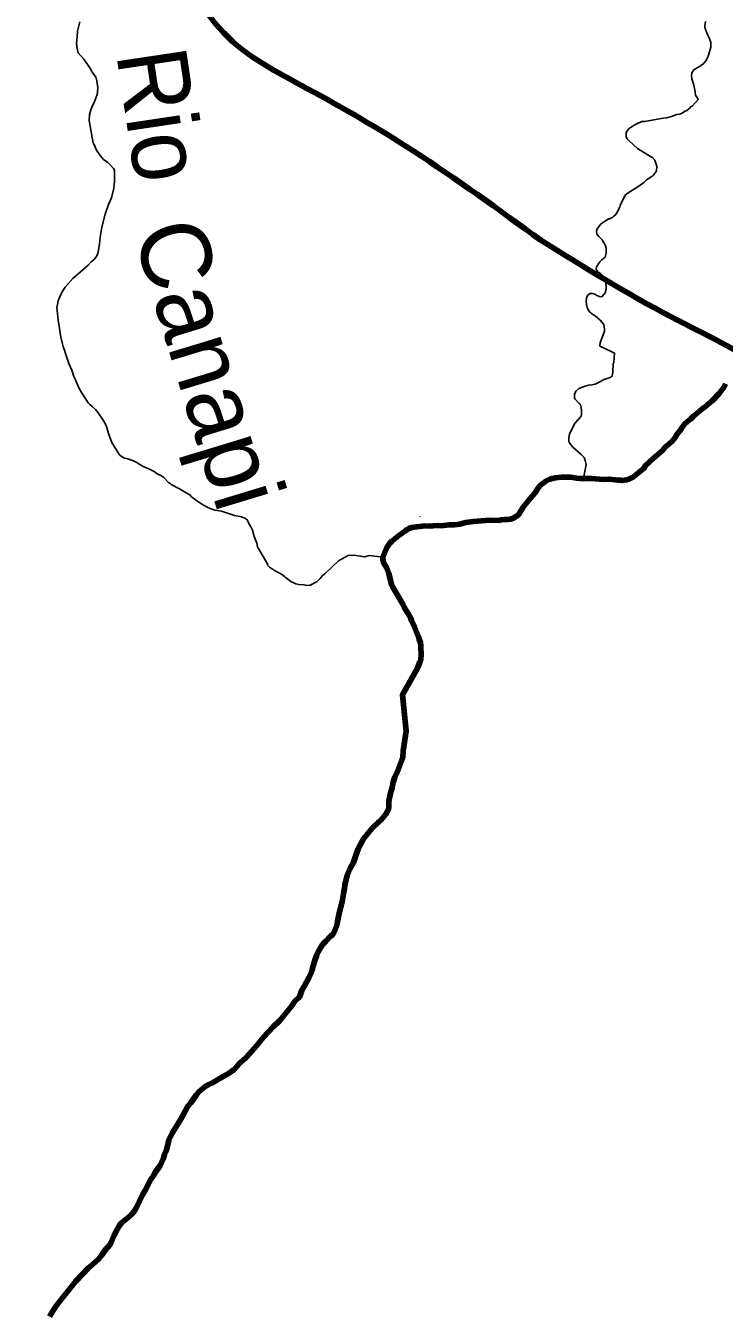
# Model space of a CAD drawing. Extents: x -1643653 to 4543381, y 1624270 to 13878484.
# Drawn here: x 652294 to 657299, y 8967746 to 8976936 of the extents above; entities that cross this region are included whole.
import ezdxf
from ezdxf.enums import TextEntityAlignment as Align

# ---------------------------------------------------------------- set-up
doc = ezdxf.new("R2010")
doc.units = 0
doc.header["$LTSCALE"] = 200
for name, color, linetype, lineweight in [('24', 7, 'Continuous', 25), ('26', 7, 'Continuous', 106), ('28', 7, 'Continuous', 53), ('60', 7, 'Continuous', 13), ('9', 7, 'Continuous', 90)]:
    doc.layers.add(name, color=color, linetype=linetype, lineweight=lineweight)
doc.layers.add('49', color=7, linetype='Continuous')

msp = doc.modelspace()

# ---------------------------------------------------------------- linework, layer by layer
at = {"layer": '24'}
for p, q in [((655116.6, 8973422.7), (655117, 8973424.3)), ((654851.3, 8973132), (654755.7, 8973142.7))]:
    msp.add_line(p, q, dxfattribs=at)
for points in [[(652799.8, 8975280.4), (652809.8, 8975302.2), (652816.1, 8975328.3), (652822.4, 8975374.6), (652826.9, 8975422.5), (652839.8, 8975493.2), (652864.5, 8975587.5), (652888.2, 8975655.6), (652908, 8975704.5), (652925.9, 8975773.4), (652929.4, 8975820.5), (652930.5, 8975902.1), (652923, 8975914.4), (652902.1, 8975937.5), (652881.4, 8975957.1), (652852.2, 8975978.9), (652827.9, 8976005.5), (652801.9, 8976045.7), (652783.3, 8976090.1), (652777.5, 8976093.8), (652748.7, 8976257.8), (652752.2, 8976297.8), (652759.6, 8976332.9), (652774.2, 8976369.2), (652784.3, 8976387.2), (652805.5, 8976443.3), (652809.5, 8976460.7), (652811.3, 8976493), (652801.1, 8976555.8), (652798.8, 8976558), (652796.5, 8976566.6), (652771.4, 8976603.6), (652757.2, 8976628.1), (652709.4, 8976696.7), (652669.3, 8976741.1), (652663.9, 8976773), (652657.8, 8976807.6), (652663.9, 8976859.5), (652664.9, 8976895.8), (652682.2, 8976964.3)], [(657164.7, 8976965.5), (657159.4, 8976934.9), (657159.4, 8976922.3), (657172.8, 8976885.3), (657195, 8976838.1), (657200.9, 8976815.4), (657201.5, 8976781.6), (657185.6, 8976725.5), (657177.3, 8976704.9), (657165.5, 8976683.5), (657144.4, 8976659), (657138.5, 8976657.5), (657133.7, 8976651.6)], [(657133.7, 8976651.6), (657080.2, 8976620), (657066.2, 8976597.4), (657063.1, 8976576.8), (657066.3, 8976556.2), (657072.5, 8976533.5), (657080.9, 8976509.9), (657090.5, 8976462.8), (657091, 8976439.3), (657110, 8976410.1), (657110.9, 8976406.4), (657067.4, 8976361), (657056.2, 8976354.8), (657053.5, 8976348.9), (657031.1, 8976329.9), (657013.6, 8976321.3), (656995.6, 8976309.4), (656979.2, 8976303.3), (656959.2, 8976299.6), (656920.6, 8976285.8), (656884.5, 8976276.8), (656845.1, 8976271.2), (656729.4, 8976250.9), (656707.8, 8976249), (656672.3, 8976234.3), (656651.5, 8976222.8), (656618, 8976199.7), (656600.5, 8976181.9), (656595.8, 8976166.3), (656594.8, 8976146.6), (656595.7, 8976138.4), (656602.4, 8976126.5), (656615.7, 8976111), (656677.7, 8976057.2), (656776.5, 8975994.6), (656782.5, 8975993.7), (656799.6, 8975973.9), (656803.7, 8975967.1), (656814.1, 8975929.4), (656813.1, 8975895.9), (656791.5, 8975865.6), (656785.6, 8975862.2), (656783.8, 8975858), (656775.5, 8975856.3), (656772.4, 8975851.8), (656742.2, 8975832.4), (656721.1, 8975813.8), (656679, 8975783.2), (656609.4, 8975739.2), (656588, 8975723), (656553.5, 8975648.5), (656550.6, 8975639.1), (656544.7, 8975630.5), (656542.4, 8975621.5), (656520.2, 8975584), (656507.8, 8975571.5), (656503.7, 8975569.7), (656500.5, 8975566.2), (656496.9, 8975565.1), (656495.3, 8975562.1), (656486.8, 8975559.7), (656479.1, 8975553.8), (656468.9, 8975552.5), (656445.8, 8975536.4), (656445.8, 8975536.4)], [(656445.8, 8975536.4), (656428.1, 8975527.1), (656412.7, 8975513.8), (656400.9, 8975501.1), (656386.7, 8975481.1), (656383.9, 8975464.5), (656385.2, 8975443.3), (656398.8, 8975427.1), (656422.7, 8975403.9), (656434, 8975387.3), (656444.5, 8975366.6), (656451.2, 8975343.8), (656452.2, 8975307.7), (656444.4, 8975279.3), (656420.2, 8975258.8), (656406.9, 8975244.3), (656382, 8975208.4), (656379.8, 8975191.2), (656391.2, 8975173.8), (656397, 8975172), (656400.5, 8975168.9), (656408.8, 8975165.1), (656442.9, 8975127.3), (656450.2, 8975105.1), (656451, 8975049), (656444.2, 8975024.3), (656423.6, 8974996.6), (656411.6, 8974995.5), (656402.2, 8974996.5), (656392.2, 8975002.6), (656384.2, 8975004.6), (656371.7, 8975013.2), (656353.6, 8975017.8), (656334.6, 8975017.5), (656320.6, 8975007.7), (656317.6, 8975003.5), (656311.8, 8974985.1)], [(654755.7, 8973142.7), (654720.6, 8973132.1), (654647.5, 8973144.9), (654604.9, 8973142), (654598.8, 8973140.5), (654534.6, 8973104.9), (654437.3, 8973012.6), (654419.5, 8972998.8), (654403.8, 8972979.2), (654381.6, 8972957.8), (654363, 8972946.1), (654335.2, 8972931.4), (654326.4, 8972929.3), (654308.8, 8972928.4), (654287.9, 8972933.5), (654250.2, 8972934.8), (654229.3, 8972940.7), (654192.4, 8972956.2), (654152.5, 8972986.8), (654147.8, 8972992.5), (654142.1, 8972995.3), (654139, 8973001.3), (654076, 8973035.9), (654041.5, 8973060), (654027.3, 8973074.1), (654028.3, 8973079.5), (653955, 8973206), (653948.8, 8973231.1), (653931.5, 8973279.1), (653918, 8973324.5), (653906.3, 8973348.1), (653892.5, 8973371.7), (653880.9, 8973398.6), (653873.4, 8973402.2), (653869.2, 8973406.6), (653838.8, 8973418.7), (653790.9, 8973428.7), (653697.5, 8973459.4), (653649.6, 8973468.4), (653604, 8973484.9), (653582.4, 8973495.6), (653556.1, 8973510.9), (653509.5, 8973541.4), (653482.9, 8973561.9), (653470.5, 8973577.6), (653442.6, 8973592.3), (653395.4, 8973620.1), (653335.2, 8973650.9), (653328.8, 8973657.6), (653317.1, 8973665.3), (653282.9, 8973700.4), (653261.2, 8973715), (653237, 8973727.3), (653213.3, 8973743.3), (653191.4, 8973755.3), (653143.5, 8973777.1), (653134.4, 8973779.3), (653111.9, 8973795.2), (653085.1, 8973811.8), (653065.5, 8973821.4), (653019.2, 8973837.3), (653002.9, 8973840.6), (652981, 8973851.6), (652965.9, 8973864.6), (652937, 8973909.3), (652911.1, 8973953), (652887.5, 8974017.3), (652874.5, 8974060.1), (652864.8, 8974083.7), (652850.2, 8974112.8), (652813.3, 8974163.9), (652794.5, 8974187.8), (652771, 8974210.2), (652753.5, 8974223.6), (652741.1, 8974236.2), (652681.1, 8974329.2), (652660, 8974375.6), (652651, 8974399.9), (652639.3, 8974423.5), (652623.5, 8974469.8), (652603.2, 8974516.9), (652579.3, 8974588.4), (652572.8, 8974612), (652562.8, 8974637.3), (652546.2, 8974706.2), (652532.2, 8974799.6), (652526.8, 8974824.9), (652519.2, 8974897.6), (652518.3, 8974918.3), (652521.3, 8974941), (652527.4, 8974967.1), (652535.4, 8974989), (652558, 8975036.1), (652577.2, 8975063.9), (652631.7, 8975125.9), (652648.1, 8975141.2), (652704.5, 8975187.2), (652741, 8975221.5), (652762.8, 8975244.2), (652783.3, 8975259.7), (652799.8, 8975280.4)], [(656311.8, 8974985.1), (656309.9, 8974965.4), (656310.9, 8974936.3), (656314.2, 8974931), (656318.5, 8974912), (656333.2, 8974887.1), (656339.6, 8974883.1), (656344.1, 8974878.5), (656345.9, 8974874.7), (656352.9, 8974872.7), (656357, 8974868.2), (656372.6, 8974857.7), (656410.2, 8974827.3), (656435.2, 8974796.3), (656440.2, 8974762.4), (656440.3, 8974749.1), (656410.3, 8974666), (656407.6, 8974643.7), (656410, 8974639.2), (656419.4, 8974636), (656511, 8974591.7), (656507.5, 8974524.4), (656501.5, 8974515), (656499.2, 8974456.9), (656494.7, 8974426.9), (656479.6, 8974416.5), (656466.4, 8974413.5), (656443.7, 8974405.2), (656396.6, 8974380.7), (656373, 8974370.1), (656349.5, 8974365.7), (656325.9, 8974363.3), (656300.7, 8974356.3), (656256.1, 8974338), (656235.1, 8974319.4), (656224.5, 8974294.9), (656226, 8974270.5), (656228.6, 8974263.7), (656258.3, 8974232.1), (656265, 8974227.3), (656269.2, 8974222.2), (656273.4, 8974202.8), (656276.5, 8974180.1), (656276.6, 8974148.4), (656268.5, 8974134.2), (656264, 8974130.4), (656262.3, 8974125), (656257.6, 8974123.2), (656253.4, 8974116.8), (656244.1, 8974109.9), (656235.6, 8974096.1), (656229.8, 8974092), (656209.8, 8974056.4), (656189, 8974012.7), (656183.6, 8973985.6), (656184.6, 8973963), (656186.9, 8973950), (656191.3, 8973947.8), (656199.2, 8973934.2), (656213.7, 8973918.7), (656274.2, 8973865.6), (656294.1, 8973843.5), (656302.2, 8973822.7), (656307.8, 8973793.6), (656289.8, 8973694.9)]]:
    msp.add_lwpolyline(points, dxfattribs=at)
at = {"layer": '24', "lineweight": 53}
for points in [[(657308, 8974372.1), (657297.1, 8974350.1), (657279, 8974323.5), (657261.3, 8974302.8), (657210.5, 8974250), (657181.7, 8974226.4), (657161.9, 8974207.7), (657140, 8974192), (657118.9, 8974173.4), (657078.2, 8974140.8), (657056.3, 8974119.3), (657035, 8974103.2), (657016, 8974086.2), (656999.6, 8974063.5), (656982.9, 8974036.6), (656963.3, 8974017.4), (656946, 8973988.7), (656926.4, 8973964.7), (656902.1, 8973940.5), (656874.4, 8973917.8), (656856.7, 8973895.3), (656791.9, 8973840.8)], [(656791.9, 8973840.8), (656791.8, 8973840.8), (656728.6, 8973781.9), (656729.8, 8973775.9), (656716.7, 8973763.4), (656647.1, 8973704.9), (656615.1, 8973689.9), (656598.4, 8973684.2), (656598.4, 8973684.2), (656567.2, 8973679.3), (656556.3, 8973683.2), (656536.3, 8973682.5), (656475.8, 8973689.6), (656432.2, 8973686.7), (656347.3, 8973694), (656260.8, 8973695.2), (656240.2, 8973697.3)], [(656240.2, 8973697.3), (656197.4, 8973704.6), (656175.9, 8973703.8), (656133.1, 8973704.7), (656090.3, 8973699.3), (656067.2, 8973694.6), (656047.4, 8973688.6), (656026.8, 8973679.3), (655983.7, 8973648.4), (655968.2, 8973630.5), (655940.3, 8973590.2), (655926.4, 8973572.3), (655907.2, 8973551.6), (655857.4, 8973488), (655825.2, 8973435), (655819.5, 8973432.4), (655817.1, 8973428.1), (655813, 8973426.4), (655807.3, 8973421.2), (655797.6, 8973417.6), (655794, 8973413), (655766.8, 8973403.9), (655745.4, 8973399.7), (655722.2, 8973400.4), (655702.5, 8973398.4), (655680.3, 8973394.3), (655616.9, 8973396.2), (655501.2, 8973386.6), (655443.3, 8973378), (655404.8, 8973367.5), (655366.2, 8973362.1), (655326.8, 8973361.9), (655289.1, 8973358.7), (655269, 8973355.7), (655249.7, 8973356.6), (655212, 8973355.5), (655191.9, 8973353.5), (655154.1, 8973354.5), (655137.5, 8973353.6), (655077.8, 8973346), (655060.3, 8973342.2), (655039.3, 8973335.4), (655029.9, 8973329.2), (655023.6, 8973328.5), (655016.9, 8973321.8), (654963.5, 8973284.3), (654916.4, 8973246.2), (654900.8, 8973228.3), (654881.6, 8973201), (654851.3, 8973132), (654852.3, 8973113.8), (654858.7, 8973088.2), (654878.1, 8973056.9), (654895, 8973014.3), (654909.2, 8972953.2), (654915.3, 8972934.7), (654923.6, 8972916.2), (654947.3, 8972875.3), (654982.1, 8972819.3), (654996.2, 8972794.1), (655005.3, 8972774), (655014.6, 8972757.2), (655044.4, 8972710.5), (655053.7, 8972692), (655056.5, 8972676.5), (655080.1, 8972632.6), (655093.2, 8972594.1), (655109.8, 8972556.3), (655111.9, 8972544), (655121.8, 8972516.9), (655124, 8972498.5), (655124.2, 8972478.4), (655127.3, 8972439.8), (655123.7, 8972391.1), (655118.2, 8972380.4), (655102.9, 8972341.9), (654992.2, 8972144.1), (655019.8, 8971884.2), (654998.6, 8971745.3), (654995, 8971695.3), (654989.7, 8971685.4), (654957.7, 8971597.4), (654937.6, 8971556.5), (654925.2, 8971519.5), (654918.6, 8971481), (654907, 8971442.4), (654896.1, 8971382.9), (654895.8, 8971344.4), (654892, 8971324.4), (654883.1, 8971306.7), (654872.7, 8971291.8), (654840.1, 8971251.1), (654818.4, 8971232.1), (654818.4, 8971232.1), (654777.1, 8971189.8), (654713.1, 8971114), (654675.8, 8971041.8), (654665.8, 8971017.4), (654650.1, 8970966.2), (654641.7, 8970946), (654616.5, 8970899.6)], [(654616.5, 8970899.6), (654597.8, 8970850.8), (654585.3, 8970804.5), (654581.2, 8970781.8), (654578.8, 8970758.3), (654572.6, 8970734.7), (654560.7, 8970664), (654554.4, 8970640.4), (654550, 8970616.9), (654542.2, 8970591.6), (654533, 8970547), (654526.8, 8970523.4), (654524.2, 8970501.2), (654508.2, 8970458.4), (654499, 8970437.8), (654493.5, 8970429), (654477.7, 8970417.1), (654443, 8970382.2), (654421.1, 8970358.3), (654389.5, 8970306.2), (654379.5, 8970284), (654365, 8970242.8), (654351.1, 8970197.8), (654345.4, 8970173.5), (654336.8, 8970149.9), (654324.7, 8970123.6), (654288, 8970056.4), (654272.8, 8970031.9), (654254.6, 8969979.6), (654230.2, 8969960.2), (654218.1, 8969945.2), (654200.3, 8969917.9), (654115.1, 8969812.6), (654066, 8969768.5), (653998.5, 8969693.6), (653949.1, 8969634.7), (653875.5, 8969551.6), (653848.1, 8969526.1), (653826.1, 8969509.2), (653807.7, 8969485.9), (653788.8, 8969465.8), (653781.7, 8969461.6), (653774.9, 8969453.3), (653733.8, 8969425.9), (653708.2, 8969413.9), (653656.8, 8969380.9), (653631.1, 8969367), (653605.4, 8969356.1), (653579.7, 8969340.1), (653534.3, 8969303.2), (653514.9, 8969279.7), (653477.3, 8969225.2), (653456.6, 8969199.3), (653405, 8969106.7), (653344.1, 8969008.1), (653319.5, 8968956.7), (653307.6, 8968905.3), (653300.6, 8968881.3), (653288.5, 8968853.8), (653281.5, 8968827.4), (653256.7, 8968776), (653222.5, 8968726.1), (653207.9, 8968699.7), (653188.9, 8968672.3), (653150.5, 8968597.6), (653133.3, 8968569.4), (653084.6, 8968470), (653068.7, 8968444.2), (653061.9, 8968437.6), (653060, 8968431.6), (653055, 8968429.5), (653045.5, 8968418.5), (652999.2, 8968380.5), (652979.1, 8968362.1), (652966, 8968345), (652949.9, 8968318.3), (652925.3, 8968271.2), (652905.8, 8968224.1), (652891.4, 8968201.3), (652870.7, 8968180.1), (652835.3, 8968129.2), (652814.8, 8968105.2), (652767.5, 8968061.3), (652745.1, 8968043.8), (652652.7, 8967947.3), (652575.9, 8967853), (652512.8, 8967770.6), (652464.1, 8967693.3)]]:
    msp.add_lwpolyline(points, dxfattribs=at)
at = {"layer": '26'}
for points in [[(593042.9, 8976356.4), (593459.4, 8976419.7), (594161.8, 8976760.1), (594545.8, 8977114.6), (594814.3, 8977291.5), (596052.8, 8977846), (596780.5, 8978160.9), (597647.4, 8978322.7), (598691.5, 8978280.2), (599825, 8978301), (600207.2, 8978324.8), (600219.9, 8978324.8), (601225.9, 8978295.2), (602040.5, 8978228.3), (602729, 8978352.6), (603275.7, 8978615.7), (603826.1, 8978691.5), (605382.2, 8979104.7), (606925.6, 8979530.7), (607614.7, 8979782.2), (608494.2, 8979905.8), (609628.7, 8980104.6), (610966.5, 8980200.8), (612239.3, 8980081.1), (613131.4, 8980179.2), (614149.6, 8980073.3), (614581.8, 8979931.6), (616361, 8979275.7), (617566.6, 8978533.2), (618237.8, 8977881.9), (618833.2, 8977319.9), (619759.6, 8976743.8), (620623, 8976295.2), (621512.5, 8975960.9), (621945, 8975870.1), (622544.2, 8975982.1), (622735.8, 8976070.3), (623374, 8976322), (623974.5, 8976675.6), (624627.1, 8977219.8), (625050.7, 8977803), (625410.5, 8978361.1), (625972.2, 8978587.6), (626239.9, 8978637.4), (628239.2, 8978616.5), (629272.1, 8978853.8), (630051.8, 8979346.6), (630703.5, 8979738.1), (631164.1, 8980105), (631534.8, 8980357.8), (632185.7, 8980596.8), (632989, 8980758.8), (633690, 8980870.4), (634328.2, 8981109.3), (634980.1, 8981526.3), (636460.7, 8982117.9), (637495.4, 8982660.5), (638159.4, 8982975.7), (638593.8, 8983228.2), (639449.6, 8983669.8), (641371.6, 8983483.9), (642032.9, 8983315.8), (642528.8, 8983186.6), (643277.3, 8982687.6), (644168, 8982544), (644675.9, 8982274.9), (645321.7, 8981636.4), (645853, 8981011.1), (646805.1, 8980473.1), (647606.1, 8980240.8), (648482.7, 8979868.5), (649626.6, 8979469.5), (650871.6, 8978943), (651404, 8978495.7), (652521.8, 8977995.2), (653308.2, 8977445.1), (653712.6, 8976883.9), (654308.9, 8976487.2), (655070.4, 8976039), (655983.7, 8975399.4)], [(655983.7, 8975399.4), (656923, 8974848.7), (657608.5, 8974464.4), (658343, 8973736.5), (658963.6, 8973136.3), (659596.6, 8972485.1), (660330.5, 8971655.5), (660495.7, 8971591.2), (661115.6, 8970863.8), (661404.1, 8970086.9), (661693.8, 8969526.2), (662110.5, 8968901.3), (662312.2, 8968544.4), (662816.6, 8967664.9), (663042.2, 8967040.8), (663203.6, 8966302.6), (663365.3, 8965640.7), (663833.2, 8965053.8), (664099.5, 8964849.2), (664772, 8964426.8), (665496.3, 8964144), (666463.4, 8964000.2), (667623.1, 8964148), (668184.3, 8964285.6), (669317.4, 8964230), (670221.1, 8964150), (671187.7, 8963917.1), (671823.3, 8963711.1), (672497.1, 8963517.5), (673386.9, 8963221.4), (674492.1, 8962733.6), (675125.5, 8962146), (675556, 8961711.9), (676150.3, 8960959.1), (676174.9, 8960921)]]:
    msp.add_spline(points, degree=3, dxfattribs=at)
at = {"layer": '28'}
for points in [[(655983.7, 8975399.4), (655070.4, 8976039), (654308.9, 8976487.2), (653712.6, 8976883.9), (653308.2, 8977445.1), (652521.8, 8977995.2), (651404, 8978495.7), (650871.6, 8978943), (649626.6, 8979469.5), (648482.7, 8979868.5), (647606.1, 8980240.8), (646805.1, 8980473.1), (645853, 8981011.1), (645321.7, 8981636.4), (644675.9, 8982274.9), (644540.6, 8982372.7)], [(676174.9, 8960921), (676150.3, 8960959.1), (675556, 8961711.9), (675125.5, 8962146), (674492.1, 8962733.6), (673386.9, 8963221.4), (672497.1, 8963517.5), (671823.3, 8963711.1), (671187.7, 8963917.1), (670221.1, 8964150), (669317.4, 8964230), (668184.3, 8964285.6), (667623.1, 8964148), (666463.4, 8964000.2), (665496.3, 8964144), (664772, 8964426.8), (664099.5, 8964849.2), (663833.2, 8965053.8), (663365.3, 8965640.7), (663203.6, 8966302.6), (663042.2, 8967040.8), (662816.6, 8967664.9), (662312.2, 8968544.4), (662110.5, 8968901.3), (661693.8, 8969526.2), (661404.1, 8970086.9), (661115.6, 8970863.8), (660495.7, 8971591.2), (660330.5, 8971655.5), (659596.6, 8972485.1), (658963.6, 8973136.3), (658343, 8973736.5), (657608.5, 8974464.4), (656923, 8974848.7), (655983.7, 8975399.4)]]:
    msp.add_spline(points, degree=3, dxfattribs=at)
at = {"layer": '60', "lineweight": 25}
msp.add_spline([(814781, 9009175.5), (814787.2, 9009173.4), (814796.9, 9009173.4), (814799.4, 9009172.4), (814805.1, 9009174.5), (814805.6, 9009176.5), (814811.7, 9009179.5), (814811.7, 9009179.5), (814801.5, 9009181), (814790.7, 9009181.5), (814784.1, 9009183.1), (814777.4, 9009185.1), (814778.4, 9009175.5)], degree=3, dxfattribs=at)
at = {"layer": '9'}
for points in [[(657308, 8974372.1), (657297.1, 8974350.1), (657279, 8974323.5), (657261.3, 8974302.8), (657210.5, 8974250), (657181.7, 8974226.4), (657161.9, 8974207.7), (657140, 8974192), (657118.9, 8974173.4), (657078.2, 8974140.8), (657056.3, 8974119.3), (657035, 8974103.2), (657016, 8974086.2), (656999.6, 8974063.5), (656982.9, 8974036.6), (656963.3, 8974017.4), (656946, 8973988.7), (656926.4, 8973964.7), (656902.1, 8973940.5), (656874.4, 8973917.8), (656856.7, 8973895.3), (656791.9, 8973840.8)], [(656791.9, 8973840.8), (656791.8, 8973840.8), (656728.6, 8973781.9), (656729.8, 8973775.9), (656716.7, 8973763.4), (656647.1, 8973704.9), (656615.1, 8973689.9), (656598.4, 8973684.2), (656598.4, 8973684.2), (656567.2, 8973679.3), (656556.3, 8973683.2), (656536.3, 8973682.5), (656475.8, 8973689.6), (656432.2, 8973686.7), (656347.3, 8973694), (656260.8, 8973695.2), (656240.2, 8973697.3)], [(656240.2, 8973697.3), (656197.4, 8973704.6), (656175.9, 8973703.8), (656133.1, 8973704.7), (656090.3, 8973699.3), (656067.2, 8973694.6), (656047.4, 8973688.6), (656026.8, 8973679.3), (655983.7, 8973648.4), (655968.2, 8973630.5), (655940.3, 8973590.2), (655926.4, 8973572.3), (655907.2, 8973551.6), (655857.4, 8973488), (655825.2, 8973435), (655819.5, 8973432.4), (655817.1, 8973428.1), (655813, 8973426.4), (655807.3, 8973421.2), (655797.6, 8973417.6), (655794, 8973413), (655766.8, 8973403.9), (655745.4, 8973399.7), (655722.2, 8973400.4), (655702.5, 8973398.4), (655680.3, 8973394.3), (655616.9, 8973396.2), (655501.2, 8973386.6), (655443.3, 8973378), (655404.8, 8973367.5), (655366.2, 8973362.1), (655326.8, 8973361.9), (655289.1, 8973358.7), (655269, 8973355.7), (655249.7, 8973356.6), (655212, 8973355.5), (655191.9, 8973353.5), (655154.1, 8973354.5), (655137.5, 8973353.6), (655077.8, 8973346), (655060.3, 8973342.2), (655039.3, 8973335.4), (655029.9, 8973329.2), (655023.6, 8973328.5), (655016.9, 8973321.8), (654963.5, 8973284.3), (654916.4, 8973246.2), (654900.8, 8973228.3), (654881.6, 8973201), (654851.3, 8973132), (654852.3, 8973113.8), (654858.7, 8973088.2), (654878.1, 8973056.9), (654895, 8973014.3), (654909.2, 8972953.2), (654915.3, 8972934.7), (654923.6, 8972916.2), (654947.3, 8972875.3), (654982.1, 8972819.3), (654996.2, 8972794.1), (655005.3, 8972774), (655014.6, 8972757.2), (655044.4, 8972710.5), (655053.7, 8972692), (655056.5, 8972676.5), (655080.1, 8972632.6), (655093.2, 8972594.1), (655109.8, 8972556.3), (655111.9, 8972544), (655121.8, 8972516.9), (655124, 8972498.5), (655124.2, 8972478.4), (655127.3, 8972439.8), (655123.7, 8972391.1), (655118.2, 8972380.4), (655102.9, 8972341.9), (654992.2, 8972144.1), (655019.8, 8971884.2), (654998.6, 8971745.3), (654995, 8971695.3), (654989.7, 8971685.4), (654957.7, 8971597.4), (654937.6, 8971556.5), (654925.2, 8971519.5), (654918.6, 8971481), (654907, 8971442.4), (654896.1, 8971382.9), (654895.8, 8971344.4), (654892, 8971324.4), (654883.1, 8971306.7), (654872.7, 8971291.8), (654840.1, 8971251.1), (654818.4, 8971232.1), (654818.4, 8971232.1), (654777.1, 8971189.8), (654713.1, 8971114), (654675.8, 8971041.8), (654665.8, 8971017.4), (654650.1, 8970966.2), (654641.7, 8970946), (654616.5, 8970899.6)], [(654616.5, 8970899.6), (654597.8, 8970850.8), (654585.3, 8970804.5), (654581.2, 8970781.8), (654578.8, 8970758.3), (654572.6, 8970734.7), (654560.7, 8970664), (654554.4, 8970640.4), (654550, 8970616.9), (654542.2, 8970591.6), (654533, 8970547), (654526.8, 8970523.4), (654524.2, 8970501.2), (654508.2, 8970458.4), (654499, 8970437.8), (654493.5, 8970429), (654477.7, 8970417.1), (654443, 8970382.2), (654421.1, 8970358.3), (654389.5, 8970306.2), (654379.5, 8970284), (654365, 8970242.8), (654351.1, 8970197.8), (654345.4, 8970173.5), (654336.8, 8970149.9), (654324.7, 8970123.6), (654288, 8970056.4), (654272.8, 8970031.9), (654254.6, 8969979.6), (654230.2, 8969960.2), (654218.1, 8969945.2), (654200.3, 8969917.9), (654115.1, 8969812.6), (654066, 8969768.5), (653998.5, 8969693.6), (653949.1, 8969634.7), (653875.5, 8969551.6), (653848.1, 8969526.1), (653826.1, 8969509.2), (653807.7, 8969485.9), (653788.8, 8969465.8), (653781.7, 8969461.6), (653774.9, 8969453.3), (653733.8, 8969425.9), (653708.2, 8969413.9), (653656.8, 8969380.9), (653631.1, 8969367), (653605.4, 8969356.1), (653579.7, 8969340.1), (653534.3, 8969303.2), (653514.9, 8969279.7), (653477.3, 8969225.2), (653456.6, 8969199.3), (653405, 8969106.7), (653344.1, 8969008.1), (653319.5, 8968956.7), (653307.6, 8968905.3), (653300.6, 8968881.3), (653288.5, 8968853.8), (653281.5, 8968827.4), (653256.7, 8968776), (653222.5, 8968726.1), (653207.9, 8968699.7), (653188.9, 8968672.3), (653150.5, 8968597.6), (653133.3, 8968569.4), (653084.6, 8968470), (653068.7, 8968444.2), (653061.9, 8968437.6), (653060, 8968431.6), (653055, 8968429.5), (653045.5, 8968418.5), (652999.2, 8968380.5), (652979.1, 8968362.1), (652966, 8968345), (652949.9, 8968318.3), (652925.3, 8968271.2), (652905.8, 8968224.1), (652891.4, 8968201.3), (652870.7, 8968180.1), (652835.3, 8968129.2), (652814.8, 8968105.2), (652767.5, 8968061.3), (652745.1, 8968043.8), (652652.7, 8967947.3), (652575.9, 8967853), (652512.8, 8967770.6), (652464.1, 8967693.3)]]:
    msp.add_lwpolyline(points, dxfattribs=at)
msp.add_spline([(637260.6, 8972975.8), (641524.5, 8971056.2), (652526.1, 8965412.7), (653164.3, 8965062.8), (670790.5, 8953770.1), (686194, 8943929.9), (696283.3, 8937647.1)], degree=3, dxfattribs=at)

# ---------------------------------------------------------------- texts
at = {"layer": '49', "width": 0.95}
msp.add_text('Rio', height=500, rotation=278.527, dxfattribs=at).set_placement((653013, 8976261.9), align=Align.CENTER)
at = {"layer": '49'}
msp.add_text('Canapi', height=500, rotation=286.879, dxfattribs=at).set_placement((653368, 8974444.7), align=Align.CENTER)

doc.saveas('drawing.dxf')
